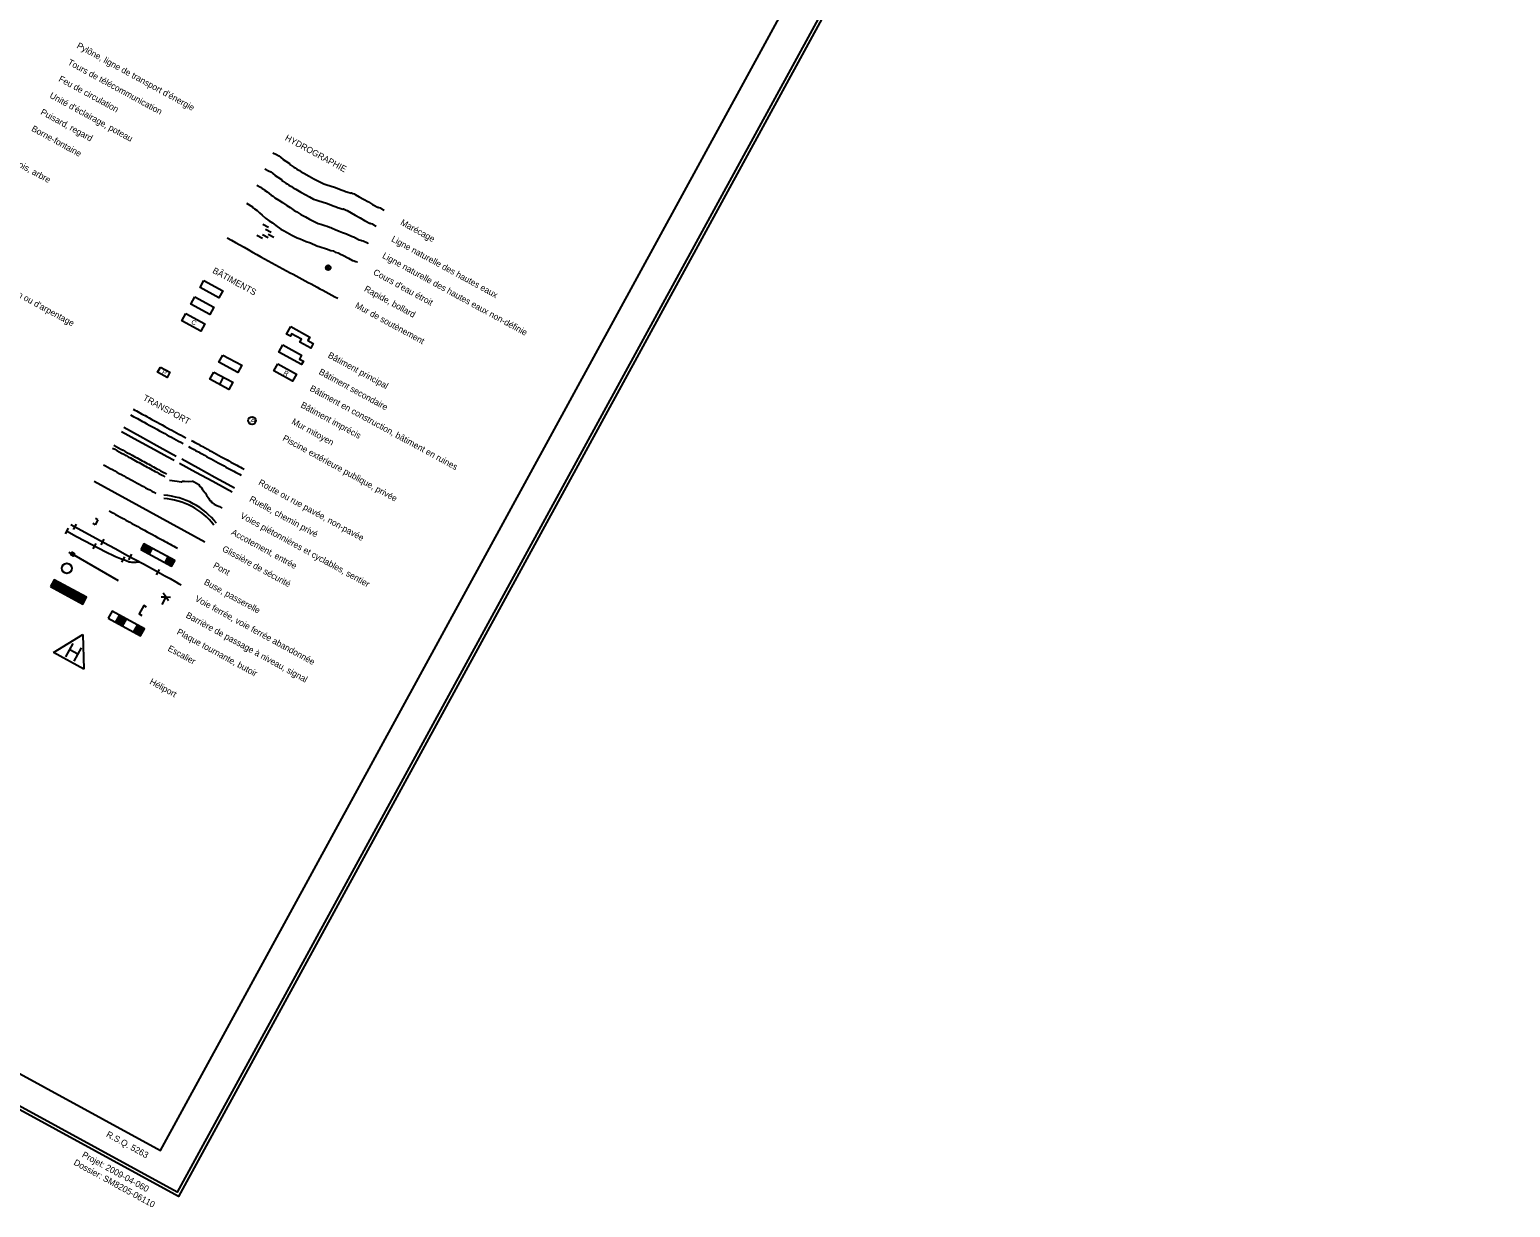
# Model space of a CAD drawing. Extents: x 219136 to 222520, y 5421589 to 5424530.
# Drawn here: x 221580 to 222520, y 5421589 to 5422336 of the extents above; entities that cross this region are included whole.
import ezdxf

# ---------------------------------------------------------------- set-up
doc = ezdxf.new("R2010")
doc.units = 0
for name, color, linetype in [('Level 10', 7, 'Continuous'), ('Level 19', 7, 'Continuous'), ('Level 21', 7, 'Continuous'), ('Level 22', 7, 'Continuous'), ('Level 23', 7, 'Continuous'), ('Level 25', 7, 'Continuous'), ('Level 26', 7, 'Continuous'), ('Level 31', 7, 'Continuous'), ('Level 38', 7, 'Continuous'), ('Level 4', 7, 'Continuous'), ('Level 6', 7, 'Continuous'), ('Level 60', 7, 'Continuous'), ('Level 63', 7, 'Continuous'), ('Level 7', 7, 'Continuous')]:
    doc.layers.add(name, color=color, linetype=linetype)

msp = doc.modelspace()

# ---------------------------------------------------------------- linework, layer by layer
at = {"layer": 'Level 10'}
for radius in [1.5, 0.6]:
    msp.add_circle((221769.86, 5422185.12), radius, dxfattribs=at)
at = {"layer": 'Level 19'}
for points in [[(221675.55, 5422061.1), (221685.95, 5422055.41), (221696.54, 5422049.63), (221704.64, 5422045.19), (221708.89, 5422042.84)], [(221676.97, 5422063.73), (221687.4, 5422058.04), (221697.96, 5422052.26), (221706.1, 5422047.82), (221710.35, 5422045.46)]]:
    msp.add_lwpolyline(points, dxfattribs=at)
for radius in [44.8, 46.8]:
    msp.add_arc((221662.21, 5421994.03), radius, 38.26981, 85.79068, dxfattribs=at)
at = {"layer": 'Level 21'}
for points in [[(221640.1, 5422083.82), (221650.53, 5422078.13), (221661.1, 5422072.35), (221669.22, 5422067.91), (221673.47, 5422065.55)], [(221638.68, 5422081.18), (221649.09, 5422075.5), (221659.68, 5422069.72), (221667.77, 5422065.29), (221672.02, 5422062.93)], [(221621.42, 5422049.59), (221691.64, 5422011.24)]]:
    msp.add_lwpolyline(points, dxfattribs=at)
for points in [[(221646.1, 5422095.38), (221654.71, 5422090.66), (221667.75, 5422083.54), (221679.44, 5422077.15)], [(221644.43, 5422091.72), (221653.06, 5422087.02), (221666.09, 5422079.89), (221677.79, 5422073.51)], [(221683.17, 5422075.46), (221690.23, 5422071.59), (221701.94, 5422065.19), (221711.82, 5422059.79), (221716.53, 5422057.23)], [(221681.29, 5422071.58), (221688.34, 5422067.74), (221700.05, 5422061.33), (221709.94, 5422055.93), (221714.65, 5422053.36)], [(221627.18, 5422060.12), (221638.71, 5422053.83), (221649.96, 5422047.69), (221660.53, 5422041.91)]]:
    msp.add_spline(points, degree=3, dxfattribs=at)
at = {"layer": 'Level 22'}
for points in [[(221669.09, 5422050.37), (221673.95, 5422049.63), (221676.65, 5422049.23), (221677, 5422049.32), (221677.44, 5422049.63), (221678.69, 5422049.76), (221681.17, 5422049.49), (221683.54, 5422049.57), (221683.88, 5422049.66), (221684.78, 5422049.17), (221687.71, 5422047.57), (221688.26, 5422046.45), (221689.49, 5422045.5), (221690.04, 5422044.38), (221690.73, 5422043.46), (221691.84, 5422042.3), (221691.95, 5422041.97), (221692.73, 5422040.74), (221692.95, 5422040.06), (221693.73, 5422039.36), (221694.17, 5422038.57), (221694.51, 5422037.56), (221695.4, 5422037.08), (221696.08, 5422036.16), (221697.53, 5422035.11), (221699.11, 5422034.23), (221700.34, 5422033.84), (221700.79, 5422033.58), (221702.16, 5422032.84), (221702.59, 5422033.15)], [(221593.54, 5421982.72), (221614.06, 5421971.51), (221616.49, 5421975.96), (221595.95, 5421987.15), (221593.54, 5421982.72)], [(221596.84, 5421986.67), (221594.42, 5421982.24), (221594.41, 5421982.23)], [(221597.71, 5421986.19), (221597.71, 5421986.18), (221595.29, 5421981.76), (221595.29, 5421981.76)], [(221598.58, 5421985.71), (221596.16, 5421981.29), (221596.16, 5421981.28)], [(221599.47, 5421985.23), (221597.05, 5421980.81), (221597.04, 5421980.8)], [(221600.34, 5421984.75), (221600.34, 5421984.74), (221597.93, 5421980.32)], [(221601.23, 5421984.28), (221601.23, 5421984.27), (221598.79, 5421979.85)], [(221602.1, 5421983.8), (221602.09, 5421983.79), (221599.68, 5421979.37), (221599.67, 5421979.36)], [(221602.97, 5421983.33), (221602.96, 5421983.31), (221600.56, 5421978.88)], [(221603.86, 5421982.85), (221603.86, 5421982.84), (221601.43, 5421978.41)], [(221604.73, 5421982.37), (221604.73, 5421982.35), (221602.32, 5421977.94), (221602.32, 5421977.93)], [(221605.61, 5421981.89), (221605.59, 5421981.87), (221603.19, 5421977.46), (221603.19, 5421977.45)], [(221606.49, 5421981.4), (221606.49, 5421981.39), (221604.07, 5421976.97)], [(221607.37, 5421980.92), (221607.36, 5421980.91), (221604.95, 5421976.49)], [(221608.24, 5421980.45), (221608.23, 5421980.43), (221605.82, 5421976.01)], [(221609.12, 5421979.97), (221609.12, 5421979.96), (221606.7, 5421975.53)], [(221609.99, 5421979.49), (221609.98, 5421979.48), (221607.58, 5421975.05)], [(221610.88, 5421979.01), (221610.88, 5421979), (221608.46, 5421974.58)], [(221611.76, 5421978.54), (221611.75, 5421978.51), (221609.34, 5421974.1)], [(221612.64, 5421978.06), (221612.62, 5421978.03), (221610.21, 5421973.62)], [(221613.52, 5421977.58), (221613.51, 5421977.56), (221611.09, 5421973.14)], [(221614.39, 5421977.1), (221614.38, 5421977.09), (221611.97, 5421972.66)], [(221615.27, 5421976.62), (221615.26, 5421976.6), (221612.84, 5421972.18)], [(221616.15, 5421976.14), (221616.14, 5421976.12), (221613.73, 5421971.7)], [(221630.24, 5421962.65), (221650.76, 5421951.43), (221653.19, 5421955.88), (221632.67, 5421967.07), (221630.24, 5421962.65)], [(221634.96, 5421960.06), (221637.39, 5421964.5)], [(221635.85, 5421959.59), (221635.85, 5421959.59), (221638.27, 5421964.03)], [(221636.72, 5421959.11), (221639.15, 5421963.55)], [(221637.59, 5421958.63), (221637.6, 5421958.64), (221640.02, 5421963.06)], [(221638.48, 5421958.15), (221638.48, 5421958.16), (221640.9, 5421962.58)], [(221639.35, 5421957.66), (221641.77, 5421962.11)], [(221646.37, 5421953.83), (221648.8, 5421958.29)], [(221647.25, 5421953.36), (221649.67, 5421957.8), (221649.68, 5421957.81)], [(221648.13, 5421952.88), (221648.13, 5421952.89), (221650.56, 5421957.31), (221650.56, 5421957.32)], [(221648.99, 5421952.4), (221649, 5421952.41), (221651.43, 5421956.83), (221651.44, 5421956.84)], [(221649.89, 5421951.91), (221652.31, 5421956.35), (221652.31, 5421956.36)]]:
    msp.add_lwpolyline(points, dxfattribs=at)
for points in [[(221632.93, 5422070.66), (221644.47, 5422064.36), (221653, 5422059.69), (221661.11, 5422055.27), (221666.29, 5422052.44)], [(221633.88, 5422072.41), (221645.43, 5422066.12), (221653.97, 5422061.45), (221662.07, 5422057.01), (221667.24, 5422054.2)]]:
    msp.add_spline(points, degree=3, dxfattribs=at)
at = {"layer": 'Level 23'}
for p, q in [((221608.49, 5422002.83), (221636.61, 5421986.61)), ((221663.77, 5421976.29), (221665.93, 5421976.2)), ((221666.79, 5421976.2), (221664.2, 5421971.44)), ((221666.3, 5421976.88), (221665.07, 5421978.66)), ((221665.93, 5421976.2), (221669.81, 5421976.08)), ((221668.5, 5421973.68), (221666.3, 5421976.88))]:
    msp.add_line(p, q, dxfattribs=at)
for points in [[(221603.21, 5422016.24), (221605.13, 5422019.76)], [(221604.17, 5422018), (221609.63, 5422014.78), (221615.94, 5422011.58), (221622.96, 5422007.84), (221630, 5422004.16), (221632.72, 5422002.85), (221634.81, 5422001.96), (221637.96, 5422000.68), (221641.15, 5421999.45), (221643.52, 5421998.53), (221644.13, 5421998.37), (221645.05, 5421998.21), (221645.52, 5421998.17), (221645.98, 5421998.17), (221647.96, 5421998.29), (221650.22, 5421998.42)], [(221606.45, 5422022.17), (221615.36, 5422017.3), (221627.4, 5422010.83), (221634.74, 5422006.95), (221642.44, 5422002.52), (221652.72, 5421997.11), (221660.34, 5421992.96), (221666.26, 5421989.57), (221669.51, 5421987.93), (221673.09, 5421985.83), (221674.88, 5421984.82), (221676.64, 5421983.8)], [(221608.18, 5422018.93), (221610.11, 5422022.44)], [(221620.77, 5422006.65), (221622.68, 5422010.18)], [(221625.73, 5422009.34), (221627.66, 5422012.86)], [(221605.37, 5422004.63), (221606.93, 5422003.72), (221607.37, 5422004.51), (221608.93, 5422003.61), (221608.04, 5422002.05), (221606.48, 5422002.95), (221606.93, 5422003.72)], [(221607.47, 5422004.25), (221608.73, 5422003.55), (221608.55, 5422003.24), (221607.28, 5422003.93), (221607.12, 5422003.62), (221608.3, 5422002.88), (221608.18, 5422002.64), (221606.93, 5422003.32), (221606.76, 5422003.02), (221607.97, 5422002.34)], [(221638.9, 5421998.19), (221640.83, 5422001.7)], [(221643.29, 5421999.75), (221645.21, 5422003.27)], [(221660.84, 5421990.17), (221662.76, 5421993.68)], [(221654.57, 5421969.77), (221652.82, 5421970.73), (221649.93, 5421965.47), (221651.69, 5421964.5)]]:
    msp.add_lwpolyline(points, dxfattribs=at)
msp.add_circle((221604, 5421994.36), 3.2, dxfattribs=at)
at = {"layer": 'Level 25'}
for p, q in [((221595.49, 5421940.95), (221614.12, 5421952.37)), ((221614.2, 5421952.38), (221614.78, 5421930.35)), ((221607.89, 5421946.62), (221603.26, 5421938.15)), ((221605.82, 5421942.88), (221611, 5421940.05)), ((221613.08, 5421943.86), (221608.43, 5421935.39)), ((221614.75, 5421930.38), (221595.45, 5421940.91))]:
    msp.add_line(p, q, dxfattribs=at)
at = {"layer": 'Level 26'}
for p, q in [((221621.98, 5422022), (221620.4, 5422022.86)), ((221623.71, 5422025.19), (221621.98, 5422022)), ((221623.71, 5422025.19), (221622.14, 5422026.06))]:
    msp.add_line(p, q, dxfattribs=at)
for points in [[(221650.92, 5422006.34), (221670.49, 5421995.65), (221672.49, 5421999.31), (221652.9, 5422009.97), (221650.92, 5422006.34)], [(221653.79, 5422009.5), (221651.81, 5422005.87)], [(221654.66, 5422009.01), (221652.68, 5422005.39)], [(221655.53, 5422008.54), (221653.56, 5422004.9)], [(221656.42, 5422008.06), (221654.44, 5422004.43)], [(221657.29, 5422007.57), (221655.31, 5422003.94)], [(221658.16, 5422007.1), (221656.19, 5422003.47)], [(221668.1, 5422001.69), (221666.1, 5421998.05)], [(221668.98, 5422001.23), (221666.98, 5421997.57)], [(221669.86, 5422000.75), (221667.86, 5421997.1)], [(221670.72, 5422000.27), (221668.74, 5421996.61)], [(221671.61, 5421999.78), (221669.62, 5421996.13)]]:
    msp.add_lwpolyline(points, dxfattribs=at)
msp.add_spline([(221630.94, 5422030.73), (221641.52, 5422024.96), (221651.63, 5422019.42), (221664.91, 5422012.18), (221674.13, 5422007.14)], degree=3, dxfattribs=at)
at = {"layer": 'Level 31'}
for points in [[(221691.03, 5422177.06), (221702.99, 5422170.52), (221700.48, 5422165.92), (221688.53, 5422172.46)], [(221685.29, 5422166.53), (221697.24, 5422160), (221694.74, 5422155.41), (221682.78, 5422161.93)], [(221679.54, 5422156), (221691.49, 5422149.46), (221688.97, 5422144.86), (221677.03, 5422151.4)], [(221746.06, 5422147.7), (221758.23, 5422141.06), (221757.02, 5422138.86), (221760.34, 5422137.04), (221758.74, 5422134.11), (221751.89, 5422137.85), (221752.9, 5422139.68), (221746.62, 5422143.11), (221745.82, 5422141.63), (221743.46, 5422142.92)], [(221741.01, 5422136.09), (221752.94, 5422129.56), (221751.63, 5422127.16), (221754.18, 5422125.77), (221752.99, 5422123.58), (221738.48, 5422131.5)], [(221703.05, 5422129.7), (221715, 5422123.16), (221712.48, 5422118.57), (221700.54, 5422125.1)], [(221737.8, 5422124.19), (221749.74, 5422117.65), (221747.24, 5422113.04), (221735.28, 5422119.59)], [(221697.32, 5422118.92), (221709.26, 5422112.39), (221706.75, 5422107.79), (221694.81, 5422114.33)]]:
    msp.add_lwpolyline(points, close=True, dxfattribs=at)
msp.add_lwpolyline([(221703.3, 5422115.66), (221700.79, 5422111.06)], dxfattribs=at)
at = {"layer": 'Level 38'}
msp.add_lwpolyline([(221663.37, 5422122.07), (221669.44, 5422118.73), (221667.64, 5422115.4), (221661.54, 5422118.73), (221663.37, 5422122.07)], dxfattribs=at)
msp.add_circle((221721.54, 5422088.1), 2.46, dxfattribs=at)
at = {"layer": 'Level 4'}
for points in [[(221729.58, 5422247.75), (221732.01, 5422246.63), (221733.39, 5422245.89), (221734.47, 5422245.07), (221736.24, 5422243.63), (221737.9, 5422242.5), (221740.15, 5422241.02), (221740.73, 5422240.22), (221741.12, 5422240.01), (221742.97, 5422238.76), (221743.76, 5422238.34), (221744.82, 5422237.5), (221746.59, 5422236.53), (221747.66, 5422235.71), (221749.23, 5422234.86), (221752.56, 5422233.04), (221755.69, 5422231.33), (221758.06, 5422230.04), (221760.6, 5422228.66), (221762.06, 5422228.08), (221763.83, 5422227.6), (221765.99, 5422226.89), (221769.43, 5422225.75), (221772.96, 5422224.28), (221774.91, 5422223.69), (221775.7, 5422223.26), (221776.58, 5422223.03), (221779.23, 5422222.29), (221779.51, 5422222.38), (221780.32, 5422221.94), (221781.2, 5422221.69), (221781.78, 5422221.38), (221784.33, 5422219.99), (221787.06, 5422218.49), (221790.2, 5422216.77), (221792.84, 5422215.11), (221793.64, 5422214.67), (221795.99, 5422213.39), (221796.48, 5422213.35), (221796.86, 5422213.14), (221797.75, 5422212.9), (221798.33, 5422212.58), (221800.3, 5422211.51)], [(221724.47, 5422237.55), (221726.81, 5422236.27), (221727.9, 5422235.45), (221729.26, 5422234.7), (221729.35, 5422234.4), (221731.22, 5422233.15), (221733.64, 5422231.1), (221734.83, 5422230.46), (221736.09, 5422229.53), (221738.54, 5422227.95), (221740.79, 5422226.48), (221743.53, 5422224.52), (221745.69, 5422223.33), (221748.21, 5422221.47), (221749.99, 5422220.5), (221752.44, 5422218.94), (221755.37, 5422217.33), (221757.93, 5422215.95), (221761.72, 5422214.09), (221763.48, 5422213.14), (221765.08, 5422212.74), (221767.61, 5422211.84), (221769.21, 5422211.45), (221770.67, 5422210.87), (221771.54, 5422210.64), (221772.34, 5422210.21), (221774.18, 5422209.43), (221776.84, 5422208.24), (221779.01, 5422207.53), (221781.55, 5422206.59), (221784.58, 5422205.19), (221786.45, 5422204.38), (221786.82, 5422204.18), (221789.39, 5422202.8), (221790.25, 5422202.56), (221790.57, 5422202.63), (221790.95, 5422202.41), (221792.04, 5422202.07), (221792.43, 5422201.85), (221794.28, 5422201.08), (221794.68, 5422200.85), (221795.26, 5422200.54)], [(221718, 5422226.06), (221721.81, 5422223.73), (221722.4, 5422222.92), (221723.17, 5422222.51), (221724.84, 5422221.36), (221726.3, 5422219.85), (221727.86, 5422218.51), (221730.11, 5422216.56), (221732.46, 5422214.82), (221734.51, 5422213.47), (221736.65, 5422211.81), (221739.8, 5422209.63), (221741.54, 5422208.66), (221743.89, 5422207.38), (221746.85, 5422205.77), (221750.26, 5422204.12), (221752.13, 5422203.37), (221755.86, 5422201.8), (221758.62, 5422200.78), (221762.72, 5422198.99), (221764.66, 5422198.4), (221768.8, 5422197.1), (221771.54, 5422196.09), (221772.92, 5422195.81), (221774.29, 5422195.06), (221776.26, 5422194.46), (221778.02, 5422193.51), (221778.69, 5422193.36), (221779.09, 5422193.13), (221782.83, 5422191.11), (221785.36, 5422189.72), (221786.24, 5422189.48), (221786.84, 5422189.16), (221787.32, 5422189.13), (221788.21, 5422188.88), (221788.41, 5422188.79)]]:
    msp.add_lwpolyline(points, dxfattribs=at)
msp.add_spline([(221705.79, 5422204.05), (221727.15, 5422192.08), (221745.73, 5422181.92), (221776, 5422165.71)], degree=3, dxfattribs=at)
at = {"layer": 'Level 6'}
for p, q in [((221724.57, 5422205.76), (221728.08, 5422203.87)), ((221728.17, 5422206.08), (221731.66, 5422204.19)), ((221728.4, 5422212.8), (221731.9, 5422210.87)), ((221730.07, 5422209.6), (221733.59, 5422207.71)), ((221731.75, 5422206.42), (221735.26, 5422204.51))]:
    msp.add_line(p, q, dxfattribs=at)
at = {"layer": 'Level 60'}
for points in [[(219135.93, 5422982.66), (219981.09, 5424529.89), (222519.95, 5423143.06), (221674.79, 5421595.83), (219135.93, 5422982.66)], [(219138.65, 5422983.46), (219981.9, 5424527.19), (222517.24, 5423142.28), (221673.99, 5421598.55), (219138.65, 5422983.46)], [(221226.31, 5421863.6), (221663.34, 5421624.89), (222488.32, 5423135.3), (222051.3, 5423374), (221226.31, 5421863.6)]]:
    msp.add_lwpolyline(points, dxfattribs=at)
at = {"layer": 'Level 7'}
msp.add_lwpolyline([(221734.68, 5422257.94), (221737.14, 5422256.83), (221738.5, 5422256.08), (221739.58, 5422255.27), (221741.34, 5422253.82), (221743.01, 5422252.68), (221745.26, 5422251.21), (221745.84, 5422250.4), (221746.23, 5422250.2), (221748.08, 5422248.96), (221748.88, 5422248.53), (221749.94, 5422247.69), (221751.69, 5422246.73), (221752.78, 5422245.91), (221754.36, 5422245.06), (221757.67, 5422243.23), (221760.82, 5422241.52), (221763.17, 5422240.24), (221765.71, 5422238.85), (221767.18, 5422238.27), (221768.94, 5422237.79), (221771.11, 5422237.09), (221774.55, 5422235.94), (221778.06, 5422234.47), (221780.02, 5422233.87), (221780.81, 5422233.45), (221781.69, 5422233.23), (221784.34, 5422232.47), (221784.63, 5422232.57), (221785.43, 5422232.14), (221786.31, 5422231.87), (221786.9, 5422231.57), (221789.44, 5422230.17), (221792.18, 5422228.68), (221795.32, 5422226.97), (221797.96, 5422225.29), (221798.75, 5422224.86), (221801.11, 5422223.58), (221801.59, 5422223.54), (221801.97, 5422223.32), (221802.87, 5422223.08), (221803.44, 5422222.77), (221805.41, 5422221.69)], dxfattribs=at)

# ---------------------------------------------------------------- texts
at = {"layer": 'Level 31'}
for s, rotation, p in [('C', 333.32807, (221682.64, 5422149.7)), ('R', 330.79215, (221741.08, 5422117.47))]:
    msp.add_text(s, height=3, rotation=rotation, dxfattribs=at).set_placement(p)
at = {"layer": 'Level 38'}
for rotation, p in [(331.81799, (221663.96, 5422117.83)), (331.32808, (221720.06, 5422087))]:
    msp.add_text('P', height=3, rotation=rotation, dxfattribs=at).set_placement(p)
at = {"layer": 'Level 63'}
for s, p in [("Pylône, ligne de transport d'énergie", (221609.94, 5422324.78)), ('Tours de télécommunication', (221604.18, 5422314.26)), ('Feu de circulation', (221598.43, 5422303.72)), ("Unité d'éclairage, poteau", (221592.68, 5422293.19)), ('Puisard, regard', (221586.93, 5422282.66)), ('Borne-fontaine', (221581.17, 5422272.13)), ('HYDROGRAPHIE', (221742.06, 5422266.29)), ('Bois, arbre', (221569.66, 5422251.07)), ('Marécage', (221815.29, 5422212.6)), ('Ligne naturelle des hautes eaux', (221809.53, 5422202.08)), ("Limite d'occupation ou d'arpentage", (221534.87, 5422187.35)), ('Ligne naturelle des hautes eaux non-définie', (221803.78, 5422191.54)), ('BÂTIMENTS', (221696.04, 5422182.04)), ("Cours d'eau étroit", (221798.03, 5422181.02)), ('Rapide, bollard', (221792.28, 5422170.48)), ('Mur de soutènement', (221786.52, 5422159.95)), ('Bâtiment principal', (221769.27, 5422128.35)), ('Bâtiment secondaire', (221763.51, 5422117.83)), ('TRANSPORT', (221651.94, 5422101.29)), ('Bâtiment en construction, bâtiment en ruines', (221757.76, 5422107.29)), ('Bâtiment imprécis', (221752.01, 5422096.77)), ('Mur mitoyen', (221746.26, 5422086.23)), ('Piscine extérieure publique, privée', (221740.51, 5422075.7)), ('Route ou rue pavée, non-pavée', (221725.18, 5422047.61)), ('Ruelle, chemin privé', (221719.43, 5422037.09)), ('Voies piétonnières et cyclables, sentier', (221713.68, 5422026.55)), ('Accotement, entrée', (221707.92, 5422016.02)), ('Glissière de sécurité', (221702.17, 5422005.49)), ('Pont', (221696.42, 5421994.96)), ('Buse, passerelle', (221690.66, 5421984.42)), ('Voie ferrée, voie ferrée abandonnée', (221684.9, 5421973.9)), ('Barrière de passage à niveau, signal', (221679.15, 5421963.36)), ('Plaque tournante, butoir', (221673.4, 5421952.84)), ('Escalier', (221667.65, 5421942.3)), ('Héliport', (221656.14, 5421921.24)), ('R.S.Q. 5263', (221628.6, 5421633.99)), ('Projet: 2009-04-060', (221613.22, 5421621.05)), ('Dossier: SM8205-06110', (221607.96, 5421616.16))]:
    msp.add_text(s, height=4, rotation=331.3379, dxfattribs=at).set_placement(p)

doc.saveas('drawing.dxf')
